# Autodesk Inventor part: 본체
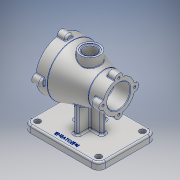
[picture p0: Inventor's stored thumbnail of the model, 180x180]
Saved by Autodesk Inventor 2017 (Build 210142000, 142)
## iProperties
Part Number: 본체
Material: 알루미늄 6061
Document SubType Name: Modeling
Designer: 222
Density: 2.7 g/cm^3
Appearance: 알루미늄 - 평지
Author: 222
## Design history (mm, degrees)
sketch "스케치1"
  geometry: L1 (-50, 0)-(50, 0); L2 (-50, 0)-(-50, 44); L3 (-50, 44)-(-30, 44); L4 (25, 27.5)-(50, 27.5); L5 (50, 27.5)-(50, 0); L6 (-30, 44)-(25, 27.5); 3 further points
  constraints: 12 end point, 2 midpoint, 2 perpendicular, 1 coincident, 1 horizontal, 1 parallel, 1 vertical
  dimensions: "d0" = 100 distance of L1.start L1.end; "d1" = 20 distance of L2.end L3.end; "d2" = 88 diameter of L3 L1; "d3" = 55 diameter of L4 L1; "d90" = 25 distance of L4.start L4.end
revolve "회전1" sketch "스케치1" stored, may be unused: angle "d5" = 90 deg
node "작업 평면1"
sketch "스케치2"
  geometry: L1 (-65, -50)-(65, -50); L2 (65, -50)-(65, 50); L3 (65, 50)-(-65, 50); L4 (-65, 50)-(-65, -50); L5 (-65, -50)-(65, 50); L6 (65, -50)-(-65, 50); 1 further point
  constraints: 12 end point, 2 midpoint, 2 parallel, 1 horizontal, 1 perpendicular
  dimensions: "d7" = 130 distance of L2.end L3.end; "d8" = 100 distance of L1.end L2.end
extrude "돌출1" join sketch "스케치2" distance "d9" = 12; taper "d10" = 0 deg
sketch "스케치3"
  geometry: L1 (-24, -4)-(24, -4); L2 (24, -4)-(24, 4); L3 (24, 4)-(-24, 4); L4 (-24, 4)-(-24, -4); L5 (-24, -4)-(24, 4); L6 (24, -4)-(-24, 4); L7 (4, -25)-(-4, -25); L8 (-4, -25)-(-4, 25); L9 (-4, 25)-(4, 25); L10 (4, 25)-(4, -25); L11 (4, -25)-(-4, 25); L12 (-4, -25)-(4, 25); 1 further point
  constraints: 24 end point, 4 midpoint, 4 parallel, 2 horizontal, 2 perpendicular
  dimensions: "d11" = 8 distance of L1.end L2.end; "d12" = 8 distance of L7.start L7.end; "d13" = 48 distance of L1.start L1.end; "d14" = 50 distance of L9.end L7.start
extrude "돌출2" join sketch "스케치3" stored distance "d15" = 12; taper "d16" = 0 deg
sketch "스케치4"
  geometry: L1 (50, 44)-(50, -44) reference; L2 (50, 0)-(-50, 0); L3 (-50, 27.5)-(-50, -27.5) reference; L4 (50, 0)-(50, 32); L5 (50, 32)-(27, 32); L6 (27, 32)-(27, 26); L7 (27, 26)-(-20, 26); L8 (-20, 26)-(-20, 20); L9 (-20, 20)-(-50, 20); L10 (-50, 0)-(-50, 20); 1 further point
  constraints: 16 end point, 5 perpendicular, 2 midpoint, 2 point on line, 1 horizontal
  dimensions: "d17" = 64 diameter of L5 L2; "d18" = 52 diameter of L7 L2; "d19" = 40 diameter of L9 L2; "d20" = 23 distance of L4.end L5.end; "d21" = 30 distance of L8.end L9.end
revolve "회전2" sketch "스케치4" stored, may be unused: angle "d22" = 90 deg
sketch "스케치5"
  geometry: C1 r 7 at (-27.5, 0); 2 further points
  constraints: 2 horizontal alignment, 1 centre point, 1 other
  dimensions: "d23" = 14 diameter of C1
extrude "돌출3" join sketch "스케치5" distance "d24" = 15; taper "d25" = 0 deg
sketch "스케치6"
  geometry: L1 (109.5, -50)-(97.5, -50) reference; L2 (97.5, -50)-(97.5, 50) reference; L3 (97.5, 50)-(109.5, 50) reference; L4 (109.5, 50)-(109.5, -50) reference; C1 r 20 at (27.5, 0) reference; A1 r 7 centre (27.5, -27.5) between (20.557, -26.609) and (34.443, -26.609) reference; A2 r 27.5 centre (27.5, 0) between (0.891, -6.943) and (20.557, -26.609) reference; A3 r 7 centre (0, 0) between (0.891, 6.943) and (0.891, -6.943) reference; A4 r 27.5 centre (27.5, 0) between (20.557, 26.609) and (0.891, 6.943) reference; A5 r 7 centre (27.5, 27.5) between (34.443, 26.609) and (20.557, 26.609) reference; A6 r 27.5 centre (27.5, 0) between (54.109, 6.943) and (34.443, 26.609) reference; A7 r 7 centre (55, 0) between (54.109, -6.943) and (54.109, 6.943) reference; A8 r 27.5 centre (27.5, 0) between (34.443, -26.609) and (54.109, -6.943) reference; 1 further point
hole "구멍1" sketch "스케치6" at (0, 0) diameter "d29" = 4.134; stored, may be unused: countersink angle "d33" = 90 deg, drill point angle "d35" = 118 deg; dims "d30" = 9, "d31" = 4, "d32" = 2, "d34" = 11
sketch "스케치7"
  geometry: C1 r 7 at (44, 0); 2 further points
  constraints: 2 horizontal alignment, 1 centre point, 1 other
  dimensions: "d39" = 14 diameter of C1
extrude "돌출4" join sketch "스케치7" distance "d40" = 15; taper "d41" = 0 deg
sketch "스케치8"
  geometry: A1 r 7 centre (0, 0) between (-0.557, -6.978) and (-0.557, 6.978) reference; 1 further point
hole "구멍2" sketch "스케치8" at (0, 0) diameter "d42" = 4.134; stored, may be unused: countersink angle "d46" = 90 deg, drill point angle "d48" = 118 deg; dims "d43" = 9, "d44" = 4, "d45" = 2, "d47" = 11
fillet "모깎기1" dims "d52" = 12
sketch "스케치9"
  geometry: L1 (65, 38)-(65, -38) reference; L2 (53, -50)-(-53, -50) reference; L3 (-65, -38)-(-65, 38) reference; L4 (-53, 50)-(53, 50) reference; L5 (24, 4)-(24, -4) reference; L6 (24, -4)-(4, -4) reference; L7 (4, -4)-(4, -25) reference; L8 (4, -25)-(-4, -25) reference; L9 (-4, -25)-(-4, -4) reference; L10 (-4, -4)-(-24, -4) reference; L11 (-24, -4)-(-24, 4) reference; L12 (-24, 4)-(-4, 4) reference; L13 (-4, 4)-(-4, 25) reference; L14 (-4, 25)-(4, 25) reference; L15 (4, 25)-(4, 4) reference; L16 (4, 4)-(24, 4) reference; C1 r 5 at (-53, 38); C2 r 5 at (-53, -38); C3 r 5 at (53, -38); C4 r 5 at (53, 38); A1 r 12 centre (53, 38) between (65, 38) and (53, 50) reference; A2 r 12 centre (53, -38) between (53, -50) and (65, -38) reference; A3 r 12 centre (-53, -38) between (-65, -38) and (-53, -50) reference; A4 r 12 centre (-53, 38) between (-53, 50) and (-65, 38) reference; 1 further point
  constraints: 4 centre point, 4 coincident
  dimensions: "d53" = 10 diameter of C1; "d54" = 10 diameter of C2; "d55" = 10 diameter of C3; "d56" = 10 diameter of C4
extrude "돌출5" cut sketch "스케치9" stored distance "d57" = 15; taper "d58" = 0 deg
node "작업 평면2"
sketch "스케치10"
  geometry: C1 r 17 at (0, 0); 1 further point
  constraints: 1 centre point, 1 coincident
  dimensions: "d60" = 34 diameter of C1
extrude "돌출6" join sketch "스케치10" stored distance "d61" = 15; taper "d62" = 0 deg
sketch "스케치11"
  geometry: 1 further point
hole "구멍3" sketch "스케치11" at (0, 0) diameter "d63" = 22; stored, may be unused: countersink angle "d67" = 90 deg, drill point angle "d69" = 118 deg; dims "d64" = 9, "d65" = 28, "d66" = 1, "d68" = 24.5
node "작업 평면3"
sketch "스케치12"
  geometry: L1 (-53, -50)-(53, -50) reference; 2 further points
  constraints: 1 vertical alignment, 1 other
  dimensions: "d71" = 10 distance from line of L1 point (0, -40)
feature "엠보싱1" sketch "스케치12" dims "d0" = 100, "d1" = 20, "d2" = 88, "d3" = 55, "d72" = 0.5, "d73" = 0, "d90" = 25
fillet "모깎기2" dims "d74" = 3
fillet "모깎기4" dims "d76" = 3
fillet "모깎기5" dims "d77" = 3
fillet "모깎기6" dims "d78" = 3
fillet "모깎기7" dims "d79" = 1
fillet "모깎기8" dims "d80" = 1
chamfer "모따기1" distance "d81" = 1; stored, may be unused: second distance "d82" = 2, angle "d83" = 45 deg
chamfer "모따기2" distance "d84" = 1; stored, may be unused: second distance "d85" = 2, angle "d86" = 45 deg
chamfer "모따기3" distance "d87" = 1; stored, may be unused: second distance "d88" = 2, angle "d89" = 45 deg
fillet "모깎기10" dims "d92" = 3
fillet "모깎기11" dims "d93" = 3
fillet "모깎기12" dims "d94" = 3
fillet "모깎기13" dims "d95" = 3
node "솔리드1"
pattern_circular "원형 패턴1" dims angle "d27" = 360 deg
pattern_circular "원형 패턴2" dims angle "d37" = 360 deg
pattern_circular "원형 패턴3" dims angle "d50" = 360 deg
node "절단 모서리 투영1"
node "절단 모서리 투영2"
other parameters: "d6" = -82, "d59" = 45, "d70" = 12.25
